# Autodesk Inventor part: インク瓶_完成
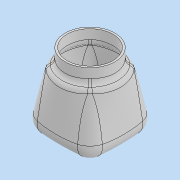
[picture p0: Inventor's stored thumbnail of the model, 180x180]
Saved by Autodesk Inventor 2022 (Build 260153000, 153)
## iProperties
Created: 2021-07
Part Number: インク瓶_完成
Material: 一般
Document SubType Name: Modeling
Designer: DesignLab
Density: 1 g/cm^3
Appearance: 既定
Author: DesignLab
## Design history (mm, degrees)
sketch "スケッチ1"
  geometry: L1 (-17.5, -17.5)-(17.5, -17.5); L2 (17.5, -17.5)-(17.5, 17.5); L3 (17.5, 17.5)-(-17.5, 17.5); L4 (-17.5, 17.5)-(-17.5, -17.5); L5 (-17.5, -17.5)-(17.5, 17.5); L6 (17.5, -17.5)-(-17.5, 17.5); 1 further point
  constraints: 12 end point, 2 midpoint, 2 parallel, 1 horizontal, 1 perpendicular
  dimensions: "d0" = 35 distance of L3.end L2.end; "d1" = 35 distance of L2.end L1.end
node "作業平面1"
sketch "スケッチ2"
  geometry: C1 r 15 at (0, 0); 1 further point
  constraints: 1 centre point, 1 coincident
  dimensions: "d3" = 30 diameter of C1
feature "ロフト1" sketch "スケッチ2" dims "d4" = 0, "d5" = 90 deg, "d6" = 0, "d7" = 90 deg
sketch "スケッチ3"
  geometry: C1 r 12.5 at (0, 0); 1 further point
  constraints: 1 centre point, 1 coincident
  dimensions: "d8" = 25 diameter of C1
extrude "押し出し1" join sketch "スケッチ3" distance "d9" = 7; taper "d10" = 0 deg
fillet "フィレット1" dims "d11" = 7
fillet "フィレット2" dims "d12" = 3
feature "シェル1" dims "d13" = 1
node "ソリッド1"
